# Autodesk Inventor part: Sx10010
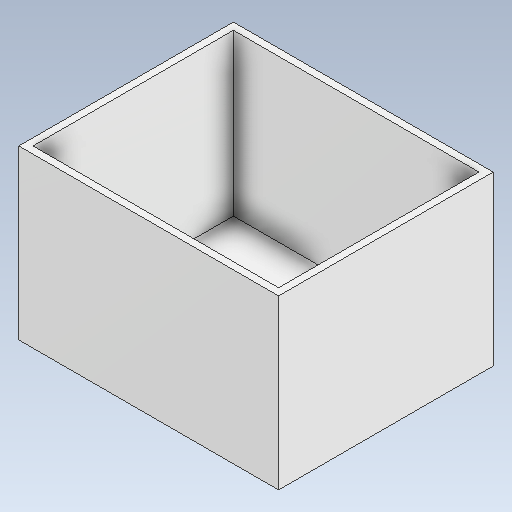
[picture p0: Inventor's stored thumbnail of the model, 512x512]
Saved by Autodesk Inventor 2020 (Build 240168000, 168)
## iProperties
Created: 2021-02
Part Number: Sx10010
Material: Generico
Document SubType Name: Modeling
Designer: zambolin
Density: 1 g/cm^3
Appearance: Default
Author: zambolin
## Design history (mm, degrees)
feature "Solido2"
node "Solido1"
